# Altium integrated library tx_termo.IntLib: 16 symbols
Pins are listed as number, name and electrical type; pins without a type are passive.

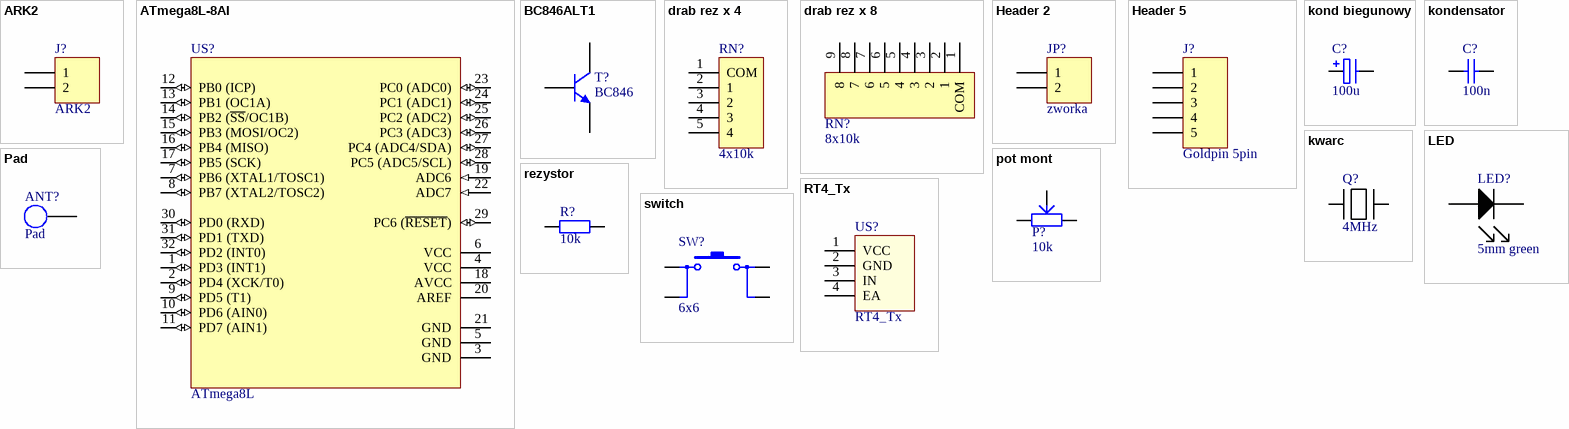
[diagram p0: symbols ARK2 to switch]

## ARK2
designator J?
footprint ARK2 3,5mm
footprint ARK2 5mm
footprint ARK2 7,5mm
pins: 1, 2

## ATmega8L-8AI
designator US?, comment ATmega8L
8-Bit AVR Microcontroller with 8K Bytes of In-System Programmable Flash Memory
footprint 32A_N (Thin QFP, 32-Leads, Body 7x7mm, Pitch 0.8mm, IPC Medium Density)
footprint 32A_L (Thin QFP, 32-Leads, Body 7x7mm, Pitch 0.8mm, IPC High Density)
footprint 32A_M (Thin QFP, 32-Leads, Body 7x7mm, Pitch 0.8mm, IPC Low Density)
3D model ATMEGA8L-32A (32-Pin Thin Quad Flat Pack 0.8 mm Pitch)
pins: 1 PD3 (INT1) (io), 2 PD4 (XCK/T0) (io), 3 GND (power), 4 VCC (power), 5 GND (power), 6 VCC (power), 7 PB6 (XTAL1/TOSC1) (io), 8 PB7 (XTAL2/TOSC2) (io), 9 PD5 (T1) (io), 10 PD6 (AIN0) (io), 11 PD7 (AIN1) (io), 12 PB0 (ICP) (io), 13 PB1 (OC1A) (io), 14 PB2 (~{SS}/OC1B) (io), 15 PB3 (MOSI/OC2) (io), 16 PB4 (MISO) (io), 17 PB5 (SCK) (io), 18 AVCC (power), 19 ADC6 (in), 20 AREF, 21 GND (power), 22 ADC7 (in), 23 PC0 (ADC0) (io), 24 PC1 (ADC1) (io), 25 PC2 (ADC2) (io), 26 PC3 (ADC3) (io), 27 PC4 (ADC4/SDA) (io), 28 PC5 (ADC5/SCL) (io), 29 PC6 (~{RESET}) (io), 30 PD0 (RXD) (io), 31 PD1 (TXD) (io), 32 PD2 (INT0) (io)

## BC846ALT1
designator T?, comment BC846
General Purpose Transistor NPN Silicon
footprint 318-08 (SOT-23; 3 Leads; Body 3.0 x 2.6 mm, inc. leads (LxW max))
simulation model BC846ALT1 (NPN)
signal-integrity model BC846ALT1
pins: 1 B, 2 E, 3 C

## drab rez x 4
designator RN?, comment 4x10k
drab rez x 4
footprint SIL5 (Connector; Header; 9 Position)
pins: 1 COM, 2 1, 3 2, 4 3, 5 4

## drab rez x 8
designator RN?, comment 8x10k
Header, 9-Pin
footprint SIL9 (Connector; Header; 9 Position)
pins: 1 COM, 2 1, 3 2, 4 3, 5 4, 6 5, 7 6, 8 7, 9 8

## Header 2
designator JP?, comment zworka
Header, 2-Pin
footprint HDR1X2 (Connector; Header; 2 Position)
signal-integrity model Connector
pins: 1, 2

## Header 5
designator J?, comment Goldpin 5pin
Header, 5-Pin
footprint HDR1X5 (Connector; Header; 5 Position)
signal-integrity model Connector
pins: 1, 2, 3, 4, 5

## kond biegunowy
designator C?, comment 100u
Polarized Capacitor
footprint Tantal B 3528-1411 (Capacitor, SM Tantalum; Body 3.5 x 2.8 mm (LxW typ))
footprint Tantal C 6032-2412 (Capacitor, SM Tantalum; Body 6.0 x 3.2 mm (LxW typ))
footprint Tantal D 7343-2917 (Capacitor, SM Tantalum; Body 7.3 x 4.3 mm (LxW typ))
footprint 2,5/5mm elektrolit
footprint 3,5/7mm elektrolit
footprint 5/10mm elektrolit
footprint 2,5/7mm elektrolit
footprint 7,5/16mm elektrolit
footprint 5/12,5mm elektrolit
footprint Tantal A 3216-1206 (Capacitor, SM Tantalum; Body 3.2 x 1.6 mm (LxW typ))
footprint A SMD elektrolit
footprint B SMD elektrolit
footprint C SMD elektrolit
footprint D SMD elektrolit
footprint E SMD elektrolit
footprint F SMD elektrolit
pins: 1, 2
1 alternate drawing of the same symbol

## kondensator
designator C?, comment 100n
footprint kond 2,5mm
footprint kond 7,5mm
footprint kond 10mm
footprint MELF-0805 (Metal Electrode Face (MELF) Resistor; Body 2 x 1.4 mm (LxDia))
footprint MELF-1206 (Metal Electrode Face (MELF) Resistor; Body 3.2 x 1.8 mm (LxDia))
footprint kond 15mm
footprint kond 5mm chudy
footprint kond 5mm gruby
footprint kond 5mm sredni
pins: 1, 2

## kwarc
designator Q?, comment 4MHz
footprint kwarc 5mm
footprint kwarc HC49
pins: 1, 2

## LED
designator LED?, comment 5mm green
footprint LED 3mm
footprint LED 5mm
footprint MELF-1206 LED (Metal Electrode Face (MELF) Resistor; Body 3.2 x 1.8 mm (LxDia))
pins: A, K

## Pad
designator ANT?
footprint pad fi 0,8mm
footprint pad fi 1,5mm
footprint pad fi 1mm
footprint pad fi 2mm
footprint pad fi 2,5mm
footprint pad fi 4mm
footprint Pad SMD 2x4mm
pins: 1

## pot mont
designator P?, comment 10k
footprint helitrim 5x10mm
footprint pot mont poziom
pins: a, b, c

## rezystor
designator R?, comment 10k
footprint rez 7,5mm
footprint rez 10mm
footprint rez 12,5mm
footprint rez 15mm
footprint rez 17,5mm
footprint MELF-0805 (Metal Electrode Face (MELF) Resistor; Body 2 x 1.4 mm (LxDia))
footprint MELF-1206 (Metal Electrode Face (MELF) Resistor; Body 3.2 x 1.8 mm (LxDia))
footprint rez_bocznik 20mm
pins: 1, 2

## RT4_Tx
designator US?
footprint RT4_Tx
pins: 1 VCC, 2 GND, 3 IN, 4 EA

## switch
designator SW?, comment 6x6
footprint tact switch 12x12
footprint tact switch 6x6
pins: 1, 2, 3, 4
